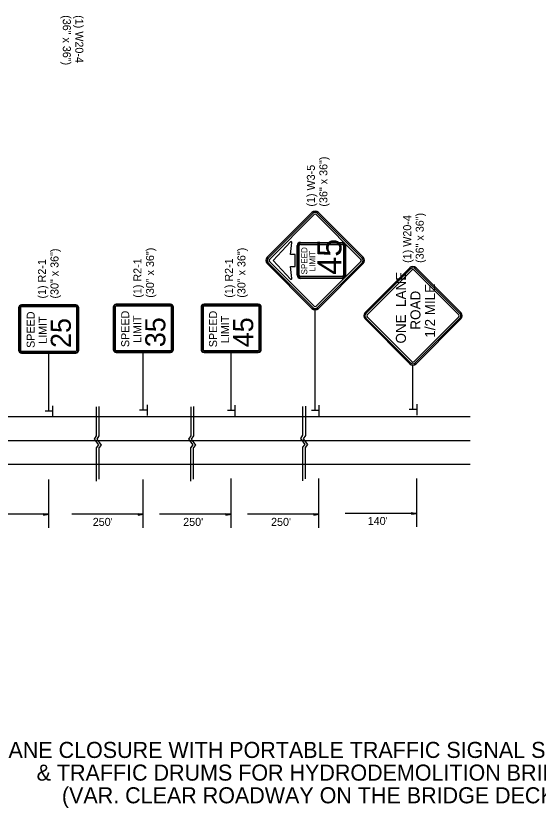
# Model space of a CAD drawing. Extents: x 1926586 to 1930787, y 596452 to 599566.
# Drawn here: x 1928330 to 1928721, y 596679 to 597271 of the extents above; entities that cross this region are included whole.
import ezdxf

# ---------------------------------------------------------------- set-up
doc = ezdxf.new("R2010")
doc.units = 0
for name, color, linetype in [('Default', 7, 'Continuous'), ('P_TC_Signs_Permanent', 7, 'Continuous'), ('P_TC_Signs_Temporary', 7, 'Continuous'), ('R_Border', 7, 'Continuous')]:
    doc.layers.add(name, color=color, linetype=linetype)

msp = doc.modelspace()

# ---------------------------------------------------------------- linework, layer by layer
at = {"layer": 'Default'}
for p, q in [((1928357.56, 596975.86), (1928352.09, 596975.86)), ((1928357.67, 596979.84), (1928357.67, 596971.83)), ((1928428.17, 596976.44), (1928422.7, 596976.44)), ((1928428.28, 596980.42), (1928428.28, 596972.41)), ((1928493.82, 596976.38), (1928488.35, 596976.38)), ((1928493.94, 596980.36), (1928493.94, 596972.36)), ((1928556.62, 596976.38), (1928551.16, 596976.38)), ((1928556.74, 596980.36), (1928556.74, 596972.36)), ((1928629.68, 596976.9), (1928624.22, 596976.9)), ((1928629.8, 596980.88), (1928629.8, 596972.87)), ((1927876.38, 596971.79), (1928531.8, 596971.74)), ((1928531.8, 596971.74), (1928669.64, 596971.73)), ((1927875.66, 596954), (1928669.64, 596953.94)), ((1927876.15, 596936.21), (1928531.8, 596936.16)), ((1928531.8, 596936.16), (1928669.64, 596936.15)), ((1928354.82, 596888.7), (1928354.82, 596924.73)), ((1928425.43, 596888.7), (1928425.43, 596924.73)), ((1928491.09, 596888.7), (1928491.09, 596925.41)), ((1928556.74, 596888.7), (1928556.74, 596925.41)), ((1928629.8, 596889.38), (1928629.8, 596925.41)), ((1928354.82, 596898.74), (1928301.42, 596898.74)), ((1928350.99, 596899.32), (1928354.82, 596898.74)), ((1928350.99, 596899.32), (1928350.99, 596898.16)), ((1928350.99, 596899.22), (1928354.18, 596898.74)), ((1928350.99, 596899.12), (1928353.52, 596898.74)), ((1928350.99, 596899.03), (1928352.88, 596898.74)), ((1928350.99, 596898.93), (1928352.23, 596898.74)), ((1928350.99, 596898.83), (1928351.59, 596898.74)), ((1928350.99, 596898.16), (1928354.82, 596898.74)), ((1928350.99, 596898.55), (1928352.23, 596898.74)), ((1928350.99, 596898.36), (1928353.52, 596898.74)), ((1928350.99, 596898.26), (1928354.18, 596898.74)), ((1928350.99, 596898.45), (1928352.88, 596898.74)), ((1928350.99, 596898.65), (1928351.59, 596898.74)), ((1928425.43, 596898.74), (1928372.03, 596898.74)), ((1928421.6, 596899.32), (1928425.43, 596898.74)), ((1928421.6, 596899.32), (1928421.6, 596898.16)), ((1928421.6, 596899.22), (1928424.79, 596898.74)), ((1928421.6, 596899.12), (1928424.13, 596898.74)), ((1928421.6, 596899.03), (1928423.49, 596898.74)), ((1928421.6, 596898.93), (1928422.84, 596898.74)), ((1928421.6, 596898.83), (1928422.2, 596898.74)), ((1928421.6, 596898.16), (1928425.43, 596898.74)), ((1928421.6, 596898.55), (1928422.84, 596898.74)), ((1928421.6, 596898.36), (1928424.13, 596898.74)), ((1928421.6, 596898.26), (1928424.79, 596898.74)), ((1928421.6, 596898.45), (1928423.49, 596898.74)), ((1928421.6, 596898.65), (1928422.2, 596898.74)), ((1928491.09, 596898.74), (1928437.68, 596898.74)), ((1928487.25, 596899.32), (1928491.09, 596898.74)), ((1928487.25, 596899.32), (1928487.25, 596898.16)), ((1928487.25, 596899.22), (1928490.45, 596898.74)), ((1928487.25, 596899.12), (1928489.79, 596898.74)), ((1928487.25, 596899.03), (1928489.15, 596898.74)), ((1928487.25, 596898.93), (1928488.5, 596898.74)), ((1928487.25, 596898.83), (1928487.86, 596898.74)), ((1928487.25, 596898.16), (1928491.09, 596898.74)), ((1928487.25, 596898.55), (1928488.5, 596898.74)), ((1928487.25, 596898.36), (1928489.79, 596898.74)), ((1928487.25, 596898.26), (1928490.45, 596898.74)), ((1928487.25, 596898.45), (1928489.15, 596898.74)), ((1928487.25, 596898.65), (1928487.86, 596898.74)), ((1928556.74, 596898.74), (1928503.34, 596898.74)), ((1928552.9, 596899.32), (1928556.74, 596898.74)), ((1928552.9, 596899.32), (1928552.9, 596898.16)), ((1928552.9, 596899.22), (1928556.1, 596898.74)), ((1928552.9, 596899.12), (1928555.44, 596898.74)), ((1928552.9, 596899.03), (1928554.8, 596898.74)), ((1928552.9, 596898.93), (1928554.15, 596898.74)), ((1928552.9, 596898.83), (1928553.51, 596898.74)), ((1928552.9, 596898.16), (1928556.74, 596898.74)), ((1928552.9, 596898.55), (1928554.15, 596898.74)), ((1928552.9, 596898.36), (1928555.44, 596898.74)), ((1928552.9, 596898.26), (1928556.1, 596898.74)), ((1928552.9, 596898.45), (1928554.8, 596898.74)), ((1928552.9, 596898.65), (1928553.51, 596898.74)), ((1928629.8, 596899.42), (1928576.4, 596899.42)), ((1928625.96, 596900), (1928629.8, 596899.42)), ((1928625.96, 596900), (1928625.96, 596898.85)), ((1928625.96, 596899.9), (1928629.16, 596899.42)), ((1928625.96, 596899.8), (1928628.5, 596899.42)), ((1928625.96, 596899.71), (1928627.86, 596899.42)), ((1928625.96, 596899.61), (1928627.21, 596899.42)), ((1928625.96, 596899.51), (1928626.57, 596899.42)), ((1928625.96, 596898.85), (1928629.8, 596899.42)), ((1928625.96, 596899.23), (1928627.21, 596899.42)), ((1928625.96, 596899.04), (1928628.5, 596899.42)), ((1928625.96, 596898.94), (1928629.16, 596899.42)), ((1928625.96, 596899.14), (1928627.86, 596899.42)), ((1928625.96, 596899.33), (1928626.57, 596899.42))]:
    msp.add_line(p, q, dxfattribs=at)
for points in [[(1928390.3, 596978.94), (1928390.3, 596957.42), (1928388.64, 596954.95), (1928391.88, 596950.52), (1928390.17, 596948.47), (1928390.17, 596923.45)], [(1928392.35, 596979.14), (1928392.35, 596957.33), (1928390.69, 596954.86), (1928393.92, 596950.43), (1928392.22, 596948.39), (1928392.22, 596924.89)], [(1928460.91, 596978.94), (1928460.91, 596957.42), (1928459.25, 596954.95), (1928462.49, 596950.52), (1928460.78, 596948.47), (1928460.78, 596923.45)], [(1928462.96, 596979.14), (1928462.96, 596957.33), (1928461.3, 596954.86), (1928464.53, 596950.43), (1928462.83, 596948.39), (1928462.82, 596924.89)], [(1928544.53, 596979.28), (1928544.53, 596957.76), (1928542.86, 596955.29), (1928546.1, 596950.86), (1928544.4, 596948.81), (1928544.39, 596923.79)], [(1928546.57, 596979.48), (1928546.57, 596957.68), (1928544.91, 596955.2), (1928548.15, 596950.77), (1928546.44, 596948.73), (1928546.44, 596925.23)]]:
    msp.add_lwpolyline(points, dxfattribs=at)
at = {"layer": 'P_TC_Signs_Permanent'}
for p, q in [((1928551.5, 597124.14), (1928518.09, 597090.73)), ((1928552.17, 597123.48), (1928518.75, 597090.07)), ((1928589.02, 597090.07), (1928555.61, 597123.48)), ((1928589.69, 597090.73), (1928556.28, 597124.14)), ((1928553.09, 597122.55), (1928519.68, 597089.14)), ((1928588.1, 597089.14), (1928554.68, 597122.55)), ((1928542.88, 597101.85), (1928574.08, 597101.85)), ((1928540.48, 597077.25), (1928540.48, 597099.45)), ((1928576.48, 597099.45), (1928576.48, 597077.25)), ((1928518.09, 597085.96), (1928551.5, 597052.55)), ((1928518.75, 597086.62), (1928552.17, 597053.21)), ((1928519.68, 597087.55), (1928553.09, 597054.14)), ((1928554.68, 597054.14), (1928588.1, 597087.55)), ((1928555.61, 597053.21), (1928589.02, 597086.62)), ((1928556.28, 597052.55), (1928589.69, 597085.96)), ((1928574.08, 597074.85), (1928542.88, 597074.85)), ((1928332.32, 597052.83), (1928332.32, 597021.33)), ((1928332.89, 597052.83), (1928332.89, 597021.33)), ((1928333.82, 597052.83), (1928333.82, 597021.33)), ((1928375.07, 597055.08), (1928334.57, 597055.08)), ((1928375.07, 597054.52), (1928334.57, 597054.52)), ((1928375.07, 597053.58), (1928334.57, 597053.58)), ((1928375.82, 597021.33), (1928375.82, 597052.83)), ((1928376.76, 597021.33), (1928376.76, 597052.83)), ((1928377.32, 597021.33), (1928377.32, 597052.83)), ((1928402.93, 597053.41), (1928402.93, 597021.91)), ((1928403.5, 597053.41), (1928403.5, 597021.91)), ((1928404.43, 597053.41), (1928404.43, 597021.91)), ((1928445.68, 597055.66), (1928405.18, 597055.66)), ((1928445.68, 597055.1), (1928405.18, 597055.1)), ((1928445.68, 597054.16), (1928405.18, 597054.16)), ((1928446.43, 597021.91), (1928446.43, 597053.41)), ((1928447.37, 597021.91), (1928447.37, 597053.41)), ((1928447.93, 597021.91), (1928447.93, 597053.41)), ((1928468.59, 597053.35), (1928468.59, 597021.85)), ((1928469.15, 597053.35), (1928469.15, 597021.85)), ((1928470.09, 597053.35), (1928470.09, 597021.85)), ((1928511.34, 597055.6), (1928470.84, 597055.6)), ((1928511.34, 597055.04), (1928470.84, 597055.04)), ((1928511.34, 597054.1), (1928470.84, 597054.1)), ((1928512.09, 597021.85), (1928512.09, 597053.35)), ((1928513.02, 597021.85), (1928513.02, 597053.35)), ((1928513.59, 597021.85), (1928513.59, 597053.35)), ((1928334.57, 597020.58), (1928375.07, 597020.58)), ((1928334.57, 597019.64), (1928375.07, 597019.64)), ((1928334.57, 597019.08), (1928375.07, 597019.08)), ((1928405.18, 597021.16), (1928445.68, 597021.16)), ((1928405.18, 597020.22), (1928445.68, 597020.22)), ((1928405.18, 597019.66), (1928445.68, 597019.66)), ((1928470.84, 597021.1), (1928511.34, 597021.1)), ((1928470.84, 597020.16), (1928511.34, 597020.16)), ((1928470.84, 597019.6), (1928511.34, 597019.6))]:
    msp.add_line(p, q, dxfattribs=at)
for points in [[(1928535.57, 597102.19), (1928522.48, 597088.31), (1928535.57, 597074.43)], [(1928536.54, 597074.89), (1928535.42, 597083.85), (1928538.98, 597083.85), (1928538.98, 597092.85), (1928535.42, 597092.85), (1928536.54, 597101.74)], [(1928574.08, 597101.25), (1928542.88, 597101.25)], [(1928542.88, 597100.35), (1928574.08, 597100.35)], [(1928541.08, 597099.45), (1928541.08, 597088.35), (1928541.08, 597077.25)], [(1928541.98, 597077.25), (1928541.98, 597088.35), (1928541.98, 597099.45)], [(1928574.98, 597099.45), (1928574.98, 597077.25)], [(1928575.88, 597077.25), (1928575.88, 597099.45)], [(1928574.08, 597076.35), (1928542.88, 597076.35)], [(1928542.88, 597075.45), (1928574.08, 597075.45)]]:
    msp.add_lwpolyline(points, dxfattribs=at)
for centre, radius, start, end in [((1928553.89, 597121.76), 3.37, 45, 135), ((1928553.89, 597121.76), 2.44, 45, 135), ((1928553.89, 597121.76), 1.13, 45, 135), ((1928535.98, 597101.81), 0.563, 352.87498, 136.68834), ((1928542.88, 597099.45), 2.4, 90, 180), ((1928542.88, 597099.45), 1.8, 90, 180), ((1928542.88, 597099.45), 0.9, 90, 180), ((1928574.08, 597099.45), 2.4, 360, 90), ((1928574.08, 597099.45), 1.8, 360, 90), ((1928574.08, 597099.45), 0.9, 360, 90), ((1928520.48, 597088.35), 3.37, 135, 225), ((1928520.48, 597088.35), 2.44, 135, 225), ((1928520.48, 597088.35), 1.13, 135, 225), ((1928587.3, 597088.35), 1.13, 315, 45), ((1928587.3, 597088.35), 2.44, 315, 45), ((1928587.3, 597088.35), 3.37, 315, 45), ((1928542.88, 597077.25), 2.4, 180, 270), ((1928542.88, 597077.25), 1.8, 180, 270), ((1928542.88, 597077.25), 0.9, 180, 270), ((1928574.08, 597077.25), 2.4, 270, 360), ((1928574.08, 597077.25), 1.8, 270, 360), ((1928574.08, 597077.25), 0.9, 270, 360), ((1928535.98, 597074.82), 0.563, 223.31166, 7.12501), ((1928334.57, 597052.83), 2.25, 90, 180), ((1928334.57, 597052.83), 1.69, 90, 180), ((1928334.57, 597052.83), 0.75, 90, 180), ((1928375.07, 597052.83), 2.25, 360, 90), ((1928375.07, 597052.83), 1.69, 360, 90), ((1928375.07, 597052.83), 0.75, 360, 90), ((1928405.18, 597053.41), 2.25, 90, 180), ((1928405.18, 597053.41), 1.69, 90, 180), ((1928405.18, 597053.41), 0.75, 90, 180), ((1928445.68, 597053.41), 2.25, 360, 90), ((1928445.68, 597053.41), 1.69, 360, 90), ((1928445.68, 597053.41), 0.75, 360, 90), ((1928470.84, 597053.35), 2.25, 90, 180), ((1928470.84, 597053.35), 1.69, 90, 180), ((1928470.84, 597053.35), 0.75, 90, 180), ((1928511.34, 597053.35), 2.25, 360, 90), ((1928511.34, 597053.35), 1.69, 360, 90), ((1928511.34, 597053.35), 0.75, 360, 90), ((1928553.89, 597054.94), 3.37, 225, 315), ((1928553.89, 597054.94), 2.44, 225, 315), ((1928553.89, 597054.94), 1.13, 225, 315), ((1928334.57, 597021.33), 2.25, 180, 270), ((1928334.57, 597021.33), 1.69, 180, 270), ((1928334.57, 597021.33), 0.75, 180, 270), ((1928375.07, 597021.33), 2.25, 270, 360), ((1928375.07, 597021.33), 1.69, 270, 360), ((1928375.07, 597021.33), 0.75, 270, 360), ((1928405.18, 597021.91), 2.25, 180, 270), ((1928405.18, 597021.91), 1.69, 180, 270), ((1928405.18, 597021.91), 0.75, 180, 270), ((1928445.68, 597021.91), 2.25, 270, 360), ((1928445.68, 597021.91), 1.69, 270, 360), ((1928445.68, 597021.91), 0.75, 270, 360), ((1928470.84, 597021.85), 2.25, 180, 270), ((1928470.84, 597021.85), 1.69, 180, 270), ((1928470.84, 597021.85), 0.75, 180, 270), ((1928511.34, 597021.85), 2.25, 270, 360), ((1928511.34, 597021.85), 1.69, 270, 360), ((1928511.34, 597021.85), 0.75, 270, 360)]:
    msp.add_arc(centre, radius, start, end, dxfattribs=at)
at = {"layer": 'P_TC_Signs_Temporary'}
for p, q in [((1928591.15, 597049.37), (1928624.56, 597082.78)), ((1928591.81, 597048.71), (1928625.23, 597082.12)), ((1928628.67, 597082.12), (1928662.08, 597048.71)), ((1928629.34, 597082.78), (1928662.75, 597049.37)), ((1928592.74, 597047.78), (1928626.15, 597081.19)), ((1928627.74, 597081.19), (1928661.16, 597047.78)), ((1928624.56, 597011.19), (1928591.15, 597044.6)), ((1928625.23, 597011.85), (1928591.81, 597045.26)), ((1928626.15, 597012.78), (1928592.74, 597046.19)), ((1928661.16, 597046.19), (1928627.74, 597012.78)), ((1928662.08, 597045.26), (1928628.67, 597011.85)), ((1928662.75, 597044.6), (1928629.34, 597011.19))]:
    msp.add_line(p, q, dxfattribs=at)
for centre, radius, start, end in [((1928626.95, 597080.4), 3.37, 45, 135), ((1928626.95, 597080.4), 2.44, 45, 135), ((1928626.95, 597080.4), 1.12, 45, 135), ((1928593.54, 597046.99), 3.37, 135, 225), ((1928593.54, 597046.99), 2.44, 135, 225), ((1928593.54, 597046.99), 1.13, 135, 225), ((1928660.36, 597046.99), 1.13, 315, 45), ((1928660.36, 597046.99), 2.44, 315, 45), ((1928660.36, 597046.99), 3.37, 315, 45), ((1928626.95, 597013.58), 3.37, 225, 315), ((1928626.95, 597013.58), 2.44, 225, 315), ((1928626.95, 597013.58), 1.12, 225, 315)]:
    msp.add_arc(centre, radius, start, end, dxfattribs=at)
at = {"layer": 'R_Border'}
for p, q in [((1928553.89, 596976.38), (1928553.89, 597051.56)), ((1928354.82, 596975.86), (1928354.82, 597019.08)), ((1928425.43, 596976.44), (1928425.43, 597019.66)), ((1928491.09, 596976.38), (1928491.09, 597019.6)), ((1928626.95, 596976.9), (1928626.95, 597010.2))]:
    msp.add_line(p, q, dxfattribs=at)

# ---------------------------------------------------------------- texts
at = {"layer": 'Default'}
for s, height, rotation, p in [("250'", 6, 359.99219, (1928387.69, 596890.06)), ("250'", 6, 359.99219, (1928455.27, 596890.07)), ("250'", 6, 359.99219, (1928520.93, 596890.07)), ("140'", 6, 359.99219, (1928593.16, 596890.76)), ('LANE CLOSURE WITH PORTABLE TRAFFIC SIGNAL SYSTEM ', 12, 360, (1928315.81, 596716.75)), ('& TRAFFIC DRUMS FOR HYDRODEMOLITION BRIDGES  ', 12, 360, (1928345.75, 596699.81)), ('(VAR. CLEAR ROADWAY ON THE BRIDGE DECKS)', 12, 360, (1928364.65, 596682.87))]:
    msp.add_text(s, height=height, rotation=rotation, dxfattribs=at).set_placement(p)
at = {"layer": 'P_TC_Signs_Permanent'}
for s, height, p in [('45', 18, (1928573.48, 597077.67)), ('SPEED', 4.5, (1928547.98, 597077.85)), ('LIMIT', 4.5, (1928553.98, 597080.16)), ('SPEED', 6, (1928344.32, 597023.01)), ('SPEED', 6, (1928414.93, 597023.59)), ('LIMIT', 6, (1928423.93, 597026.68)), ('SPEED', 6, (1928480.59, 597023.53)), ('LIMIT', 6, (1928489.59, 597026.62)), ('LIMIT', 6, (1928353.32, 597026.1)), ('25', 15, (1928371.32, 597023)), ('35', 15, (1928441.93, 597023.57)), ('45', 15, (1928507.59, 597023.52))]:
    msp.add_text(s, height=height, rotation=90, dxfattribs=at).set_placement(p)
at = {"layer": 'P_TC_Signs_Temporary'}
for s, p in [('ONE  LANE', (1928621.7, 597026.29)), ('1/2 MILE', (1928643.45, 597030.67)), ('ROAD', (1928632.57, 597036.68))]:
    msp.add_text(s, height=7.5, rotation=90, dxfattribs=at).set_placement(p)
at = {"layer": 'R_Border'}
for s, height, rotation, p in [('(36" x 36")', 5.9996, 270, (1928365.32, 597271.52)), ('(1) W20-4', 6, 270, (1928374.68, 597271.52)), ('(36" x 36")', 6, 90, (1928563.02, 597128.55)), ('(1) W3-5', 6, 90, (1928553.66, 597128.55)), ('(1) W20-4', 6, 90, (1928625.63, 597086.5)), ('(36" x 36")', 6, 90, (1928635, 597086.5)), ('(30" x 36")', 5.9996, 90, (1928362.11, 597059.88)), ('(30" x 36")', 5.9996, 90, (1928433.47, 597060.48)), ('(30" x 36")', 5.9996, 90, (1928501.8, 597060.48)), ('(1) R2-1', 6, 90, (1928352.75, 597059.88)), ('(1) R2-1', 6, 90, (1928424.1, 597060.48)), ('(1) R2-1', 6, 90, (1928492.44, 597060.48))]:
    msp.add_text(s, height=height, rotation=rotation, dxfattribs=at).set_placement(p)

doc.saveas('drawing.dxf')
